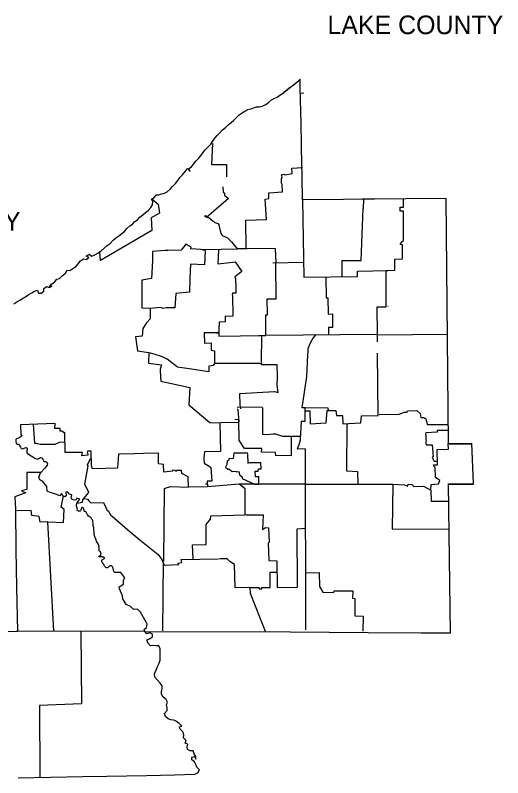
# Model space of a CAD drawing. Extents: x 0 to 42.4, y 0 to 22.
# Drawn here: x 38.72 to 42.38, y 8.31 to 14.04 of the extents above; entities that cross this region are included whole.
import ezdxf

# ---------------------------------------------------------------- set-up
doc = ezdxf.new("R2010")
doc.units = 0
doc.layers.add('Default', color=7, linetype='Continuous')

msp = doc.modelspace()

# ---------------------------------------------------------------- linework, layer by layer
at = {"layer": 'Default'}
for p, q in [((41.9544, 12.6609), (41.9716, 10.8212)), ((41.9545, 12.6609), (41.9716, 10.8212)), ((39.812, 11.2883), (40.0318, 11.2415)), ((40.0318, 11.2415), (40.0241, 11.1124)), ((40.0241, 11.1124), (40.1825, 10.9785)), ((40.8677, 10.989), (40.861, 10.8481)), ((40.7921, 10.8763), (40.8639, 10.8763)), ((41.9716, 10.8212), (42.1469, 10.824)), ((41.9716, 10.8212), (42.1469, 10.824)), ((41.9731, 10.8168), (42.1493, 10.8195)), ((42.1469, 10.824), (42.1604, 10.5199)), ((42.1469, 10.824), (42.1604, 10.5199)), ((39.2995, 10.6319), (39.2924, 10.6536)), ((41.9724, 10.518), (42.1604, 10.5199)), ((41.9724, 10.518), (42.0871, 10.5192)), ((41.9724, 10.518), (41.9883, 9.3965)), ((41.9724, 10.518), (41.9883, 9.3965)), ((41.9738, 10.5135), (42.0889, 10.5147)), ((42.0889, 10.5147), (42.1617, 10.5154))]:
    msp.add_line(p, q, dxfattribs=at)
for points in [[(39.3668, 12.2722), (39.3668, 12.2722), (39.4103, 12.3091), (39.4332, 12.3235), (39.455, 12.3499), (39.476, 12.3652), (39.497, 12.3808), (39.5194, 12.3991), (39.5406, 12.4146), (39.5574, 12.4356), (39.5791, 12.4557), (39.5994, 12.4681), (39.6167, 12.4884), (39.6377, 12.5013), (39.6562, 12.5218), (39.6778, 12.5395), (39.6991, 12.5564), (39.7182, 12.5709), (39.7382, 12.5931), (39.75, 12.6139), (39.7523, 12.6364), (39.7425, 12.6579), (39.7626, 12.6702), (39.7795, 12.6898), (39.7993, 12.6887), (39.8194, 12.6968), (39.8409, 12.7018), (39.8605, 12.7127), (39.8827, 12.7325), (39.9005, 12.7526), (39.923, 12.7743), (39.9404, 12.7977), (39.956, 12.8189), (39.976, 12.8404), (39.9975, 12.866), (40.0146, 12.886), (40.0328, 12.8658), (40.0232, 12.886), (40.0435, 12.9006), (40.0593, 12.9206), (40.0757, 12.9431), (40.096, 12.9634), (40.1158, 12.9867), (40.1302, 13.0063), (40.1471, 13.0264), (40.1677, 13.0505), (40.1882, 13.0705), (40.2042, 13.0925), (40.2202, 13.1145), (40.2376, 13.134), (40.2577, 13.1562), (40.2777, 13.1765), (40.2997, 13.1958), (40.3194, 13.2156), (40.3405, 13.2326), (40.3607, 13.2512), (40.381, 13.2701), (40.4016, 13.2897), (40.4233, 13.3056), (40.4455, 13.3176), (40.4677, 13.33), (40.4894, 13.3357), (40.5102, 13.3426), (40.5309, 13.35), (40.5538, 13.3505), (40.5741, 13.356), (40.6009, 13.3668), (40.6212, 13.3839), (40.6446, 13.4019), (40.6636, 13.4142), (40.6878, 13.4231), (40.7078, 13.4381), (40.7286, 13.4498), (40.8601, 13.5565)], [(40.8593, 13.5579), (40.8384, 13.5362), (40.8186, 13.5188), (40.7978, 13.5033), (40.7772, 13.4901), (40.7563, 13.4735), (40.7388, 13.4617)], [(40.8589, 13.5565), (40.8589, 13.5579), (40.8593, 13.5579)], [(40.8589, 13.5563), (40.8589, 13.5579), (40.8593, 13.5579)], [(40.8589, 13.5563), (40.8589, 13.5579), (40.8593, 13.5579)], [(40.8594, 13.557), (40.8594, 13.5576), (40.8595, 13.5577)], [(41.9545, 12.6609), (41.6539, 12.6585), (41.4193, 12.6567), (41.3265, 12.6559), (41.1869, 12.6543), (40.8773, 12.6519), (40.8747, 12.8285), (40.8699, 13.0383), (40.8692, 13.0615), (40.8665, 13.2267), (40.8611, 13.4928), (40.8601, 13.5574)], [(40.8877, 13.4536), (40.8678, 13.4506)], [(40.2004, 13.0751), (40.1946, 12.9163), (40.307, 12.9183), (40.307, 12.8249)], [(40.6791, 12.1815), (40.6753, 12.2826), (40.4552, 12.2858), (40.4512, 12.4993), (40.6075, 12.5051), (40.5966, 12.6559), (40.6248, 12.6624), (40.6259, 12.7041), (40.7271, 12.7121), (40.7243, 12.7657), (40.7202, 12.7781), (40.7202, 12.7877), (40.7202, 12.8085), (40.7243, 12.8249), (40.7202, 12.8385), (40.7202, 12.8385), (40.7369, 12.8455), (40.7482, 12.84), (40.8007, 12.8491), (40.7987, 12.8896), (40.8768, 12.8948)], [(40.2784, 12.7498), (40.2813, 12.7068), (40.2906, 12.7054), (40.2917, 12.6879), (40.3225, 12.6612), (40.1564, 12.5189), (40.1405, 12.5297), (40.1491, 12.5349), (40.1696, 12.5189), (40.1734, 12.5189), (40.2058, 12.4906), (40.2116, 12.4884), (40.2194, 12.482), (40.2276, 12.4795), (40.2345, 12.4771), (40.2416, 12.4736), (40.2483, 12.4638), (40.2517, 12.4514), (40.2639, 12.3993), (40.2708, 12.3893), (40.2798, 12.3812), (40.2999, 12.3747), (40.3147, 12.3654), (40.3295, 12.3511), (40.3448, 12.3359), (40.3898, 12.2815), (40.144, 12.2757), (40.1273, 12.2772), (40.1479, 12.2757), (40.0381, 12.2826), (40.0399, 12.2972), (40.0309, 12.3018), (40.0022, 12.3192), (39.9671, 12.2735), (39.8652, 12.2717), (39.8425, 12.2717), (39.7512, 12.2642), (39.7495, 12.1938), (39.7425, 12.0597), (39.6716, 12.0478), (39.6716, 11.9828), (39.6716, 11.964), (39.67, 11.8401), (39.7332, 11.8377), (39.7332, 11.7583), (39.7055, 11.7279), (39.6791, 11.6849), (39.6726, 11.627), (39.6241, 11.6222), (39.6383, 11.5164), (39.722, 11.5047), (39.7199, 11.4255), (39.8172, 11.4119), (39.8089, 11.3799), (39.8113, 11.3178), (39.812, 11.2883)], [(39.7454, 12.6593), (39.7929, 12.618), (39.8039, 12.5524), (39.7404, 12.5172), (39.7454, 12.4211), (39.3611, 12.1951), (39.3557, 12.2623)], [(40.8773, 12.6519), (40.8882, 12.0709), (41.2919, 12.0752), (41.2919, 12.1146), (41.5213, 12.1199)], [(41.3348, 12.5869), (41.3381, 12.6548)], [(41.6377, 12.3461), (41.6377, 12.5671), (41.6127, 12.5671), (41.6127, 12.5958), (41.6372, 12.5958), (41.6377, 12.6579)], [(41.1758, 12.0752), (41.1749, 12.196), (41.3174, 12.196), (41.3343, 12.5862)], [(41.4417, 11.6384), (41.438, 11.8468), (41.506, 11.8471), (41.506, 12.1199), (41.5702, 12.1223), (41.5702, 12.2058), (41.6296, 12.2077), (41.6296, 12.3129), (41.6126, 12.3153), (41.6236, 12.3351)], [(41.6236, 12.3351), (41.6377, 12.3461)], [(38.7088, 11.8714), (38.7308, 11.8847), (38.753, 11.8977), (38.7745, 11.9107), (38.7961, 11.9241), (38.8176, 11.938), (38.843, 11.9532), (38.8646, 11.9647), (38.8859, 11.9721), (38.8931, 11.9511), (38.9145, 11.9497), (38.9351, 11.9647), (38.9334, 11.9866), (38.9554, 12.0005), (38.9773, 11.9934), (38.9933, 12.0041), (38.9764, 11.9989), (38.9943, 12.0213), (39.0145, 12.0342), (39.0318, 12.0559), (39.0518, 12.0609), (39.073, 12.0819), (39.0957, 12.101), (39.11, 12.1225), (39.1303, 12.1205), (39.1518, 12.1371), (39.1735, 12.1504), (39.1929, 12.1719), (39.2105, 12.1927), (39.2323, 12.2074), (39.252, 12.2029), (39.2733, 12.2189), (39.2518, 12.2294), (39.2738, 12.2444), (39.2943, 12.228), (39.3184, 12.239), (39.3404, 12.2506), (39.3611, 12.2669), (39.3668, 12.2722)], [(40.1464, 12.2695), (40.1424, 12.1636), (40.0362, 12.168), (40.0306, 12.0597), (40.0295, 11.9573), (39.9268, 11.9483), (39.9184, 11.8401), (39.854, 11.8401), (39.8301, 11.8344), (39.8129, 11.8432), (39.7332, 11.836)], [(40.2467, 12.2757), (40.2419, 12.1716), (40.3546, 12.1843), (40.3705, 12.1853), (40.4209, 12.1127), (40.3682, 12.0735), (40.3751, 12.0585), (40.3767, 11.991), (40.3767, 11.9508), (40.3514, 11.9508), (40.3503, 11.9368), (40.3515, 11.9335), (40.3546, 11.7768), (40.2965, 11.7754), (40.2972, 11.7349), (40.2521, 11.7339), (40.25, 11.6792), (40.25, 11.6527)], [(40.388, 12.285), (40.4584, 12.2858)], [(40.6025, 11.633), (40.6025, 11.7876), (40.6145, 11.7876), (40.6118, 11.907), (40.6803, 11.9079), (40.6766, 12.1752)], [(40.8868, 12.1803), (40.6558, 12.1766)], [(41.0541, 12.0721), (41.0553, 11.9144), (41.067, 11.9156), (41.0709, 11.7938), (41.1023, 11.7943), (41.1035, 11.6935), (41.0718, 11.6921), (41.0727, 11.6396)], [(41.5189, 11.8518), (41.5201, 11.8518)], [(40.2321, 11.653), (40.1395, 11.6527), (40.1404, 11.5742), (40.1911, 11.5768), (40.1911, 11.5232), (40.2176, 11.5174), (40.2152, 11.4286)], [(40.2491, 11.6516), (40.2321, 11.6522), (40.2491, 11.6508), (40.2483, 11.6287), (40.5703, 11.633)], [(40.5508, 11.6322), (40.6025, 11.6327)], [(40.5701, 11.4343), (40.5718, 11.6308)], [(41.4406, 11.6398), (40.6021, 11.633)], [(40.8969, 11.0892), (40.8758, 11.0889), (40.9092, 11.3238), (40.9171, 11.4849), (40.9193, 11.5124), (40.9212, 11.5348), (40.9303, 11.5587), (40.9403, 11.5828), (40.9501, 11.6005), (40.9586, 11.6119), (40.9713, 11.6286), (40.9808, 11.6396)], [(41.4413, 11.5852), (41.4423, 11.6384), (41.9669, 11.6435)], [(40.2176, 11.4227), (40.2058, 11.4071), (40.1739, 11.4014), (40.1734, 11.3589), (40.0259, 11.3821), (39.9397, 11.3937), (39.86, 11.4541), (39.8251, 11.4732), (39.7641, 11.4923), (39.7265, 11.5021)], [(40.9007, 11.0663), (40.8985, 11.0667), (40.9339, 11.0663), (40.9355, 10.9696), (41.0546, 10.9753), (41.0622, 11.0689), (41.1279, 11.0687), (41.1326, 11.0327), (41.1775, 11.0326), (41.1818, 10.9684), (41.3169, 10.9773), (41.32, 11.0281), (41.4451, 11.0327), (41.442, 11.4995)], [(40.2163, 11.4243), (40.5727, 11.4236)], [(40.4135, 11.0828), (40.4094, 11.1129), (40.4058, 11.198), (40.6672, 11.2117), (40.6952, 11.204), (40.6878, 11.2587), (40.6892, 11.3212), (40.6865, 11.411), (40.5703, 11.4126), (40.5718, 11.4293)], [(40.3867, 11.082), (40.3922, 11.0768), (40.4002, 10.984)], [(40.5755, 11.093), (40.3872, 11.0909)], [(40.576, 11.0925), (40.5777, 10.8911)], [(40.8988, 10.9894), (40.8975, 11.0897), (41.0654, 11.0925), (41.0718, 11.0691)], [(41.4535, 11.0398), (41.6033, 11.0407), (41.6442, 11.056), (41.664, 11.0563), (41.6654, 11.0675), (41.737, 11.0687), (41.7618, 11.046), (41.7676, 11.0169), (41.7895, 11.0169), (41.8038, 11.0062), (41.8136, 10.9649), (41.9733, 10.9644)], [(40.403, 10.84), (40.3984, 10.999), (40.3689, 11.0007)], [(39.2924, 10.6536), (39.291, 10.7643), (39.2614, 10.7634), (39.2599, 10.7508), (39.2656, 10.7464), (39.2647, 10.7338), (39.2193, 10.7293), (39.2246, 10.7526), (39.0943, 10.7526), (39.0921, 10.9032), (39.0811, 10.9011), (39.0811, 10.9088), (39.0718, 10.9128), (39.0571, 10.9128), (39.0578, 10.9345), (39.016, 10.9326), (39.0191, 10.9713), (38.7597, 10.9624), (38.7623, 10.8897), (38.7692, 10.8837), (38.7666, 10.8763), (38.7515, 10.863)], [(38.8549, 10.9655), (38.8633, 10.8236), (38.8773, 10.824), (38.9072, 10.8161), (39.0186, 10.8149), (39.0527, 10.8324), (39.0909, 10.8347)], [(40.1825, 10.9785), (40.2571, 10.9766), (40.2607, 10.7613), (40.1405, 10.7575), (40.1374, 10.7102), (40.1383, 10.6725), (40.177, 10.6498), (40.1877, 10.6398), (40.1968, 10.5383), (40.1626, 10.5373), (40.1641, 10.4953), (40.0208, 10.4934), (40.0189, 10.5713), (39.9707, 10.5965), (39.9683, 10.6175), (39.9314, 10.6181), (39.9316, 10.614), (39.923, 10.6135), (39.923, 10.6181), (39.9008, 10.62), (39.9008, 10.6125), (39.8349, 10.6066), (39.833, 10.6634), (39.7946, 10.6686), (39.7946, 10.7489), (39.6822, 10.7467), (39.6165, 10.7446), (39.495, 10.7403), (39.4874, 10.6359), (39.2995, 10.6319)], [(40.2607, 10.9785), (40.3978, 10.9821)], [(40.8684, 10.989), (40.8988, 10.9883)], [(41.2954, 10.514), (41.2935, 10.6089), (41.2102, 10.6128), (41.2143, 10.9682)], [(40.5777, 10.8911), (40.6118, 10.8892), (40.6577, 10.8945), (40.6756, 10.8937), (40.7264, 10.8758), (40.7923, 10.8758)], [(41.9716, 10.9186), (41.8886, 10.9186), (41.8888, 10.9052), (41.8055, 10.9016), (41.8027, 10.8923), (41.8043, 10.8846), (41.8055, 10.8768), (41.8041, 10.8648), (41.8041, 10.8563), (41.8055, 10.8491), (41.8057, 10.8439), (41.8055, 10.8276), (41.8027, 10.8248), (41.8038, 10.8178), (41.8086, 10.8123), (41.853, 10.8123), (41.8588, 10.72), (41.8511, 10.7185), (41.8564, 10.7063), (41.8659, 10.6894), (41.8912, 10.6891)], [(38.7499, 10.8629), (38.7296, 10.8562), (38.7227, 10.8507), (38.7239, 10.8328), (38.7269, 10.8238), (38.7362, 10.8169), (38.7448, 10.8152), (38.7515, 10.8051), (38.7594, 10.7927), (38.764, 10.7841), (38.7714, 10.781), (38.7802, 10.783), (38.7902, 10.7878), (38.8002, 10.7915), (38.8079, 10.7853), (38.8079, 10.7746), (38.8057, 10.766), (38.806, 10.7572), (38.8093, 10.7491), (38.8179, 10.741), (38.8723, 10.7078), (38.8835, 10.7033), (38.8926, 10.7051), (38.9012, 10.7114), (38.91, 10.7169), (38.9193, 10.7133), (38.9262, 10.704), (38.9308, 10.6935), (38.9346, 10.686), (38.9463, 10.6851), (38.9561, 10.6817), (38.9613, 10.6689), (38.9585, 10.6574), (38.9422, 10.636)], [(40.7921, 10.8763), (40.7921, 10.7825), (40.7923, 10.7293), (40.6765, 10.7317), (40.676, 10.7534), (40.5706, 10.7567), (40.5724, 10.7825), (40.4431, 10.7841), (40.4051, 10.84)], [(40.899, 10.781), (40.8393, 10.7798)], [(40.9028, 9.4213), (40.9014, 10.7798)], [(41.8415, 10.47), (41.844, 10.514), (41.8991, 10.5176), (41.9084, 10.5421), (41.8762, 10.566), (41.8736, 10.641), (41.8659, 10.6459), (41.8611, 10.6601), (41.8921, 10.661), (41.89, 10.7765), (41.9735, 10.7782), (41.9716, 10.8212)], [(40.4669, 10.7481), (40.3627, 10.7495), (40.3574, 10.7082), (40.325, 10.7061), (40.3235, 10.6958), (40.3111, 10.6913), (40.3094, 10.6632), (40.2991, 10.6426), (40.3178, 10.6292), (40.3235, 10.6319), (40.3486, 10.6118), (40.3801, 10.6125), (40.3818, 10.608), (40.3987, 10.6097), (40.4033, 10.5848), (40.4233, 10.5713), (40.4243, 10.5588), (40.5176, 10.5149), (40.5484, 10.5168), (40.5491, 10.5696), (40.5235, 10.5703), (40.5224, 10.6142), (40.544, 10.6145), (40.5465, 10.6298), (40.5681, 10.6305), (40.5656, 10.6749), (40.4679, 10.6758)], [(40.4689, 10.6717), (40.4672, 10.7441)], [(39.2349, 10.4078), (39.2726, 10.4522), (39.2422, 10.5151), (39.2666, 10.6529), (39.2613, 10.6598), (39.2857, 10.7082), (39.2917, 10.7083)], [(38.9086, 10.6027), (38.8072, 10.6027), (38.8069, 10.4765), (38.7675, 10.4646), (38.7969, 10.451), (38.7155, 10.4216)], [(39.0532, 10.4275), (39.0353, 10.4343), (39.0317, 10.4385), (38.9809, 10.4529), (38.9602, 10.4632), (38.9561, 10.499), (38.9236, 10.5386), (38.9053, 10.5483), (38.8973, 10.5682), (38.91, 10.602), (38.9422, 10.636)], [(39.8349, 9.9361), (39.84, 10.4837), (39.8602, 10.4918), (39.8875, 10.4973), (40.0208, 10.4934)], [(40.1596, 10.5147), (40.1479, 10.5147)], [(40.4011, 10.5149), (40.1641, 10.4953)], [(40.8971, 10.5149), (40.4011, 10.5149)], [(40.4469, 10.2849), (40.4457, 10.4808), (40.4023, 10.5147)], [(40.8971, 10.5149), (41.5561, 10.5144), (41.5509, 10.1767), (41.974, 10.18)], [(41.5561, 10.5144), (41.6437, 10.5095), (41.6676, 10.5009), (41.6728, 10.5163), (41.7003, 10.5123), (41.7146, 10.4984), (41.7864, 10.5018), (41.8415, 10.47), (41.8444, 10.3877), (41.976, 10.3868)], [(39.0095, 9.4119), (38.9642, 10.2316), (39.0814, 10.2278), (39.0859, 10.3263), (39.0647, 10.3429), (39.0821, 10.4283)], [(39.1823, 10.3732), (39.1816, 10.3731), (39.2036, 10.4023), (39.1811, 10.4106), (39.1735, 10.3956), (39.154, 10.397), (39.1449, 10.4027), (39.1392, 10.4137), (39.1449, 10.4366), (39.1268, 10.4402), (39.1127, 10.4583), (39.0995, 10.4567), (39.1029, 10.4271), (39.0922, 10.4206), (39.0766, 10.428), (39.0659, 10.4457), (39.0539, 10.4275)], [(38.7155, 10.4216), (38.7203, 10.3307), (38.7246, 10.0216), (38.7276, 9.7421), (38.7351, 9.4096), (38.5403, 9.4041)], [(39.1826, 10.3734), (39.2244, 10.3806), (39.2265, 10.397), (39.2342, 10.4071)], [(39.2346, 10.4077), (39.2618, 10.4027), (39.2716, 10.3899), (39.2872, 10.3756), (39.3819, 10.3786), (39.4113, 10.3135), (39.4186, 10.3168), (39.4308, 10.293), (39.4358, 10.2849), (39.447, 10.2741), (39.565, 10.1731), (39.6552, 10.0977), (39.743, 10.0271), (39.7924, 9.9867), (39.7989, 9.98), (39.8208, 9.9492), (39.8208, 9.9468)], [(38.9642, 10.2316), (38.9069, 10.2295), (38.8985, 10.2731), (38.8436, 10.281), (38.838, 10.3187), (38.7305, 10.3156)], [(40.0566, 9.9547), (40.05, 10.0597), (40.155, 10.0619), (40.155, 10.2134), (40.1858, 10.2529), (40.1877, 10.2779), (40.4455, 10.2849)], [(40.4512, 10.2858), (40.582, 10.2849), (40.576, 10.1755), (40.5997, 10.1889), (40.6233, 10.1865), (40.6262, 10.0789), (40.6193, 10.0712), (40.6248, 9.9418), (40.6842, 9.9399), (40.6878, 9.7401), (40.8412, 9.7408), (40.8384, 10.1805), (40.903, 10.1853)], [(39.8208, 9.9492), (39.838, 9.9082), (39.9473, 9.9122), (39.9421, 9.9222), (39.9714, 9.9268), (39.9671, 9.9487), (40.2467, 9.9559)], [(39.8277, 9.4132), (39.833, 9.9328)], [(40.4854, 9.7397), (40.372, 9.7361), (40.3667, 9.9122), (40.3328, 9.9349), (40.3058, 9.9604), (40.3094, 9.9559), (40.2536, 9.9559)], [(39.6927, 9.4091), (39.6889, 9.4236), (39.7043, 9.4397), (39.7099, 9.4644), (39.7027, 9.4783), (39.6612, 9.5538), (39.6389, 9.5764), (39.6106, 9.5745), (39.5864, 9.5964), (39.5537, 9.6118), (39.5272, 9.6537), (39.5246, 9.6759), (39.5015, 9.7287), (39.5008, 9.7451), (39.532, 9.7647), (39.533, 9.79), (39.5337, 9.7955), (39.5421, 9.8118), (39.5127, 9.8526), (39.5008, 9.8528), (39.4681, 9.8509), (39.4599, 9.8602), (39.4532, 9.8932), (39.4428, 9.9024)], [(40.6006, 9.4081), (40.4872, 9.6941), (40.4854, 9.7389), (40.5531, 9.7397), (40.5531, 9.7292), (40.572, 9.7292), (40.572, 9.7404), (40.6338, 9.7401), (40.6338, 9.8549), (40.6865, 9.8549)], [(40.904, 9.8495), (41.003, 9.8509), (41.0064, 9.7463), (41.0298, 9.7034), (41.114, 9.7027), (41.1148, 9.7149), (41.2558, 9.7141), (41.2541, 9.6587), (41.2709, 9.6571), (41.272, 9.527), (41.3337, 9.5249), (41.3313, 9.4103)], [(38.7291, 9.4122), (39.6895, 9.4148)], [(39.2132, 9.4094), (39.2172, 8.8647), (38.901, 8.852), (38.9034, 8.3138)], [(39.4079, 8.3219), (39.7056, 8.3279), (39.9168, 8.3328), (40.0698, 8.3364), (40.0903, 8.3479), (40.103, 8.3684), (40.0827, 8.389), (40.0757, 8.41), (40.0657, 8.4298), (40.0461, 8.4448), (40.0452, 8.4656), (40.0658, 8.4708), (40.0757, 8.45), (40.0774, 8.4708), (40.0636, 8.4909), (40.0566, 8.5117), (40.0347, 8.5128), (40.0146, 8.5212), (40.0123, 8.5422), (40.0152, 8.5625), (39.9955, 8.5696), (40.0025, 8.5895), (39.9839, 8.6102), (39.987, 8.6324), (39.981, 8.6532), (39.96, 8.6727), (39.9511, 8.6935), (39.9714, 8.6966), (39.9511, 8.7171), (39.9306, 8.7315), (39.9099, 8.7436), (39.8891, 8.7446), (39.8681, 8.7522), (39.848, 8.7709), (39.8418, 8.7916), (39.8602, 8.8153), (39.86, 8.837), (39.8566, 8.8577), (39.864, 8.8775), (39.8526, 8.899), (39.8318, 8.9165), (39.8184, 8.9382), (39.8178, 8.9585), (39.8227, 8.9785), (39.8221, 9), (39.8092, 9.0214), (39.7877, 9.0436), (39.769, 9.0668), (39.7662, 9.0883), (39.7731, 9.109), (39.7838, 9.1301), (39.7912, 9.1515), (39.801, 9.1721), (39.8091, 9.1935), (39.8079, 9.2145), (39.8091, 9.2368), (39.8089, 9.258), (39.8092, 9.2785), (39.7986, 9.3007), (39.7769, 9.301), (39.7561, 9.3024), (39.7351, 9.3009), (39.7156, 9.3246), (39.7082, 9.3461), (39.7292, 9.3547), (39.75, 9.369), (39.7514, 9.3891), (39.7306, 9.3988), (39.7089, 9.3905), (39.6924, 9.4096)], [(39.6927, 9.4091), (40.7852, 9.407), (41.3708, 9.4012), (41.7685, 9.3984), (41.9883, 9.3986)], [(38.7425, 8.31), (38.7425, 8.31), (39.2275, 8.3183), (39.4079, 8.3212)]]:
    msp.add_lwpolyline(points, dxfattribs=at)
msp.add_arc((40.4737, 10.9341), 0.3973, 337.043, 347.4937, dxfattribs=at)
for points in [[(39.2501, 10.3096), (39.2477, 10.3123), (39.2409, 10.3096), (39.2363, 10.3197), (39.232, 10.3335), (39.2246, 10.3407), (39.2196, 10.3395), (39.217, 10.3354), (39.2155, 10.3306), (39.2146, 10.3269), (39.2129, 10.3238), (39.2096, 10.3158), (39.2076, 10.3135), (39.205, 10.3127), (39.1974, 10.3123), (39.1909, 10.3142), (39.1866, 10.3164), (39.1859, 10.3269), (39.1816, 10.3435), (39.1804, 10.3595), (39.1816, 10.3739)], [(39.3504, 10.0141), (39.3495, 10.0399), (39.348, 10.0512), (39.3442, 10.0624), (39.3191, 10.1146), (39.316, 10.1268), (39.3132, 10.1395), (39.31, 10.1791), (39.3048, 10.212), (39.3026, 10.2331), (39.2986, 10.2473), (39.2924, 10.2571), (39.2893, 10.2648), (39.2767, 10.2705), (39.2649, 10.2815), (39.2554, 10.2999), (39.2499, 10.3097)], [(39.4428, 9.9024), (39.4299, 9.9015), (39.4198, 9.8919), (39.4007, 9.8891), (39.3943, 9.8953), (39.3819, 9.916), (39.3742, 9.9254), (39.3692, 9.9433), (39.3716, 9.9478), (39.3795, 9.9518), (39.3865, 9.9561), (39.3896, 9.9607), (39.3886, 9.9641), (39.3795, 9.9671), (39.3742, 9.9691), (39.3626, 9.9691), (39.3564, 9.9691), (39.3514, 9.9691), (39.3497, 9.9712), (39.3477, 9.9738), (39.3514, 9.976), (39.3618, 9.9814), (39.3626, 9.9853), (39.3647, 9.9944), (39.3647, 9.9968), (39.3618, 9.9991), (39.3602, 10.0041), (39.3564, 10.0103), (39.3497, 10.0156)]]:
    msp.add_spline(points, degree=3, dxfattribs=at)

# ---------------------------------------------------------------- texts
for s, p in [('LAKE COUNTY', (41.0652, 13.8964)), ('CUYAHOGA COUNTY', (36.8452, 12.4205))]:
    msp.add_text(s, height=0.14, dxfattribs=at).set_placement(p)

doc.saveas('drawing.dxf')
